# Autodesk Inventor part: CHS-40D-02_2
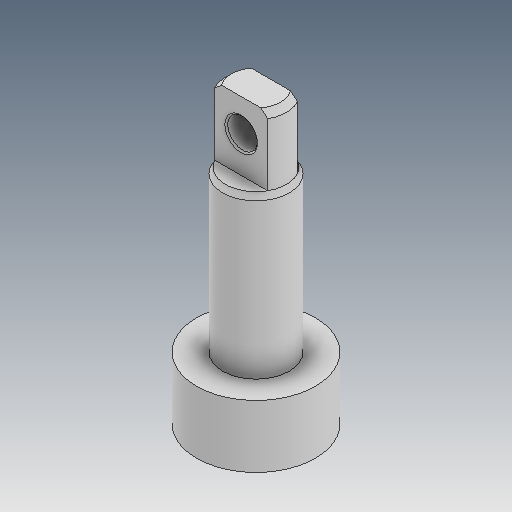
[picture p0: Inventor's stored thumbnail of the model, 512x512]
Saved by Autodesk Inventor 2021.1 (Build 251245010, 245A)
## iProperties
Created: 2019-04
Part Number: CHS-40D-02_2
Material: Ogólny
Document SubType Name: Modeling
Designer: user
Density: 1 g/cm^3
Appearance: Domyślna
Author: user
Revision Number: ÈÎºÎ
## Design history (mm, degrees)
feature "ÊäÈë1"
feature "ÊäÈë2"
node "Bryła1"
node "Bryła2"
